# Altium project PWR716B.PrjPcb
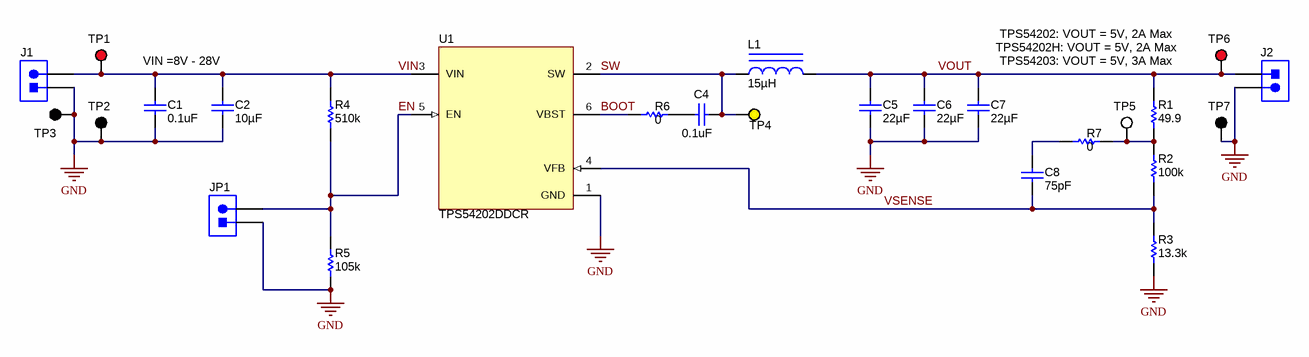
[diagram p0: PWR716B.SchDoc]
TID: N/A; TechSupport: http://www.ti.com/support; SCH_Rev: B; PRJ_Title: TPS54202EVM-716; PRJ_Number: PWR716; PRJ_Engineer: Abull Yang; PRJ_Customer: Public Release; PCB_Rev: B; PCB_Layout: Abull Yang; CopyrightYear: 2019
2 sheets, 40 parts. Net scope: global (net labels, ports and power ports of the same name join across sheets).
Board file: PWR716B.PcbDoc
Sheets:
  PWR716B.SchDoc
  PWR716B_Hardware.SchDoc

## Sheet PWR716B.SchDoc: PWR716
size 431 x 279 mm; VersionControl_RevNumber: A; Date: Not shown in title block; ApprovedBy: Not shown in title block; CheckedBy: Not shown in title block; Author: Not shown in title block; CompanyName: Not shown in title block; DrawnBy: Abull Yang; Engineer: Abull Yang; Organization: Not shown in title block; Address1: Not shown in title block; Address2: Not shown in title block; Address3: Not shown in title block; Address4: Not shown in title block; DocumentNumber: 1; Revision: Use project parameter SCH_Rev; SheetNumber: 1; SheetTotal: 1; PageSetup: Record=PageOptions¦CenterHorizontal=True¦CenterVertical=True¦PrintScale=1.00¦XCorrection=1.00¦YCorrection=1.00¦PrintKind=0¦BorderSize=5000000¦LeftOffset=0¦BottomOffset=0¦Orientation=2¦PaperLength=1000¦PaperWidth=1000¦Scale=100¦PaperSource=15¦PrintQuality=600¦MediaType=1¦DitherType=10¦PaperKind=Letter¦PrintScaleMode=1

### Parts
C1  ValueDisplayed: 0.1uF  [0603]  (hidden comment: GRM188R61E104KA01D)
C2  ValueDisplayed: 10µF  [1210]  (hidden comment: GRM32ER7YA106KA12L)
C4  0.1uF  [0603]
C5  ValueDisplayed: 22µF  [1210]  (hidden comment: GRM32ER71E226KE15L)
C6  ValueDisplayed: 22µF  [1210]  (hidden comment: GRM32ER71E226KE15L)
C7  ValueDisplayed: 22µF  [1210]  (hidden comment: GRM32ER71E226KE15L)
C8  ValueDisplayed: 75pF  [0603]  (hidden comment: GRM1885C1H750JA01D)
J1  ED555/2DS  [TERM_BLK_ED555-2DS]  (value not drawn)
J2  ED555/2DS  [TERM_BLK_ED555-2DS]  (value not drawn)
JP1  TSW-102-07-G-S  [TSW-102-07-G-S]  (value not drawn)
L1  ValueDisplayed: 15µH  [WE-PD-1050]  (hidden comment: 7447714150)
R1  ValueDisplayed: 49.9  [0603]  (hidden comment: CRCW060349R9FKEA)
R2  ValueDisplayed: 100k  [0603]  (hidden comment: CRCW0603100KFKEA)
R3  ValueDisplayed: 13.3k  [0603]  (hidden comment: CRCW060313K3FKEA)
R4  ValueDisplayed: 510k  [0603]  (hidden comment: CRCW0603510KJNEA)
R5  ValueDisplayed: 105k  [0603]  (hidden comment: CRCW0603105KFKEA)
R6  value 0  [0603]  (hidden comment: ERJ-3GEY0R00V)
R7  value 0  [0603]  (hidden comment: ERJ-3GEY0R00V)
TP1  5000  [Keystone5000]  (value not drawn)
TP2  5001  [Keystone5001]  (value not drawn)
TP3  5001  [Keystone5001]  (value not drawn)
TP4  5004  [Keystone5004]  (value not drawn)
TP5  5002  [Keystone5002]  (value not drawn)
TP6  5000  [Keystone5000]  (value not drawn)
TP7  5001  [Keystone5001]  (value not drawn)
U1  TPS54202DDCR  [DDC0006A_N]

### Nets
GND: C1.2 C2.1 C5.1 C6.1 C7.1 J1.1 J2.2 JP1.1 R3.1 R5.1 TP2.1 TP3.1 TP7.1 U1.1(GND)
BOOT: R6.1 U1.6(VBST)
EN: JP1.2 R4.1 R5.2 U1.5(EN)
SW: C4.2 L1.1 TP4.1 U1.2(SW)
VIN: C1.1 C2.2 J1.2 R4.2 TP1.1 U1.3(VIN)
VOUT: C5.2 C6.2 C7.2 J2.1 L1.2 R1.2 TP6.1
VSENSE: C8.2 R2.1 R3.2 U1.4(VFB)
NetC4_1: C4.1 R6.2
NetC8_1: C8.1 R7.1
NetR1_1: R1.1 R2.2 R7.2 TP5.1

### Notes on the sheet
- TPS54202: VOUT = 5V, 2A Max
- VIN =8V - 28V
- TPS54202H: VOUT = 5V, 2A Max
- TPS54203: VOUT = 5V, 3A Max

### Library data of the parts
C1 C4 = GRM188R61E104KA01D: CAP, CERM, 0.1uF, 25V, +/-10%, X5R, 0603; Manufacturer: MuRata; Polarized: N; CompType: Capacitor; U/M: EA; Cap_F: 0.0000001; Tolerance_%: 10; Value1: Unknown; VDC_V: 25; TaMin_C: -55; TaMax_C: 85
C2 = GRM32ER7YA106KA12L: CAP, CERM, 10 µF, 35 V, +/- 10%, X7R, 1210; Manufacturer: MuRata; Polarized: N; CompType: Capacitor; Value: 10uF; U/M: EA; Cap_F: 0.00001; Tolerance_%: 10; Value1: Unknown; VDC_V: 35; Value2: 35V; TaMin_C: -55; TaMax_C: 125
C5-C7 = GRM32ER71E226KE15L: CAP, CERM, 22 µF, 25 V, +/- 10%, X7R, 1210; Manufacturer: MuRata; Polarized: N; CompType: Capacitor; Value: 22uF; U/M: EA; Cap_F: 0.000022; Tolerance_%: 10; Value1: Unknown; VDC_V: 25; Value2: 25V; TaMin_C: -55; TaMax_C: 125
C8 = GRM1885C1H750JA01D: CAP, CERM, 75 pF, 50 V, +/- 5%, C0G/NP0, 0603; Manufacturer: MuRata; Polarized: N; CompType: Capacitor; Value: 75pF; U/M: EA; Cap_F: 0.000000000075; Tolerance_%: 5; Value1: Unknown; VDC_V: 50; Value2: 50V; TaMin_C: -55; TaMax_C: 125
J1 J2 = ED555/2DS: Terminal Block, 6A, 3.5mm Pitch, 2-Pos, TH; Manufacturer: On-Shore Technology; SymbolCreator: a0412235; CompType: Connector; U/M: EA
JP1 = TSW-102-07-G-S: Header, 100mil, 2x1, Gold, TH; Manufacturer: Samtec; SymbolCreator: a0412235; U/M: EA
L1 = 7447714150: Inductor, Shielded Drum Core, Ferrite, 15 µH, 3.5 A, 0.036 ohm, SMD; Manufacturer: Wurth Elektronik; Value: 15uH; Ind_H: 15.0E-6; Imax_A: 3.5; Irms: 3.5A @ 40C rise; Isat: 4.1A @ 10% inductance drop; DCR_ohm: 0.036; Value2: 3.5A; AEC Category: Q200
R1 = CRCW060349R9FKEA: RES, 49.9, 1%, 0.1 W, 0603; Manufacturer: Vishay-Dale; CompType: Resistor; Value: 49.9; Value_Code: 49R9; Tolerance_%: 1; Power_W: 0.1; Value2: 0.1W; VDC_V: 75; TempCo: 100 ppm/C; EIA_Code: E96; U/M: EA
R2 = CRCW0603100KFKEA: RES, 100 k, 1%, 0.1 W, 0603; Manufacturer: Vishay-Dale; CompType: Resistor; Value: 100k; Res_ohm: 100000; Tolerance_%: 1; Power_W: 0.1; Value2: 0.1W; VDC_V: 75; TempCo: 100 ppm/C; EIA_Code: E96; U/M: EA; AEC Category: Q200
R3 = CRCW060313K3FKEA: RES, 13.3 k, 1%, 0.1 W, 0603; Manufacturer: Vishay-Dale; CompType: Resistor; Value: 13.3k; Res_ohm: 13300; Value_Code: 13k3; Tolerance_%: 1; Power_W: 0.1; Value2: 0.1W; VDC_V: 75; TempCo: 100 ppm/C; EIA_Code: E96; U/M: EA
R4 = CRCW0603510KJNEA: RES, 510 k, 5%, 0.1 W, 0603; Manufacturer: Vishay-Dale; CompType: Resistor; Value: 510k; Res_ohm: 510000; Tolerance_%: 5; Power_W: 0.1; Value2: 0.1W; VDC_V: 75; TempCo: 200 ppm/C; EIA_Code: E24; U/M: EA
R5 = CRCW0603105KFKEA: RES, 105 k, 1%, 0.1 W, 0603; Manufacturer: Vishay-Dale; CompType: Resistor; Value: 105k; Res_ohm: 105000; Tolerance_%: 1; Power_W: 0.1; Value2: 0.1W; VDC_V: 75; TempCo: 100 ppm/C; EIA_Code: E96; U/M: EA
R6 R7 = ERJ-3GEY0R00V: RES, 0 ohm, 5%, 0.1W, 0603; Manufacturer: Panasonic; CompType: Resistor; Value_Code: 0000; Tolerance_%: 5; Power_W: 0.1; VDC_V: 50; TempCo: 600 ppm/C; EIA_Code: E24; U/M: EA
TP1 TP6 = 5000: Test Point, Miniature, Red, TH; Manufacturer: Keystone; CompType: Test Point Loop; U/M: EA
TP2 TP3 TP7 = 5001: Test Point, Miniature, Black, TH; Manufacturer: Keystone; CompType: Test Point Loop; U/M: EA
TP4 = 5004: Test Point, Miniature, Yellow, TH; Manufacturer: Keystone; CompType: Test Point Loop; U/M: EA
TP5 = 5002: Test Point, Miniature, White, TH; Manufacturer: Keystone; CompType: Test Point Loop; U/M: EA
U1 = TPS54202DDCR: 4.5-V TO 28-V INPUT, 2-A OUTPUT, EMI FRIENDLY SYNCHRONUOUS STEP-DOWN CONVERTOR, DDC0006A; Alternate Manufacturer: Texas Instruments; SymbolCreator: Altium; CompType: IC; U/M: EA

## Sheet PWR716B_Hardware.SchDoc
size 431 x 279 mm; Date: Not shown in title block; ApprovedBy: Not shown in title block; CheckedBy: Not shown in title block; Author: Not shown in title block; CompanyName: Not shown in title block; Engineer: Not shown in title block; Organization: Not shown in title block; Address1: Not shown in title block; Address2: Not shown in title block; Address3: Not shown in title block; Address4: Not shown in title block; DocumentNumber: 1; Revision: Use project parameter SCH_Rev; SheetNumber: 1; SheetTotal: 1; PageSetup: Record=PageOptions¦CenterHorizontal=True¦CenterVertical=True¦PrintScale=1.00¦XCorrection=1.00¦YCorrection=1.00¦PrintKind=0¦BorderSize=5000000¦LeftOffset=0¦BottomOffset=0¦Orientation=2¦PaperLength=1000¦PaperWidth=1000¦Scale=100¦PaperSource=15¦PrintQuality=600¦MediaType=1¦DitherType=10¦PaperKind=Letter¦PrintScaleMode=1
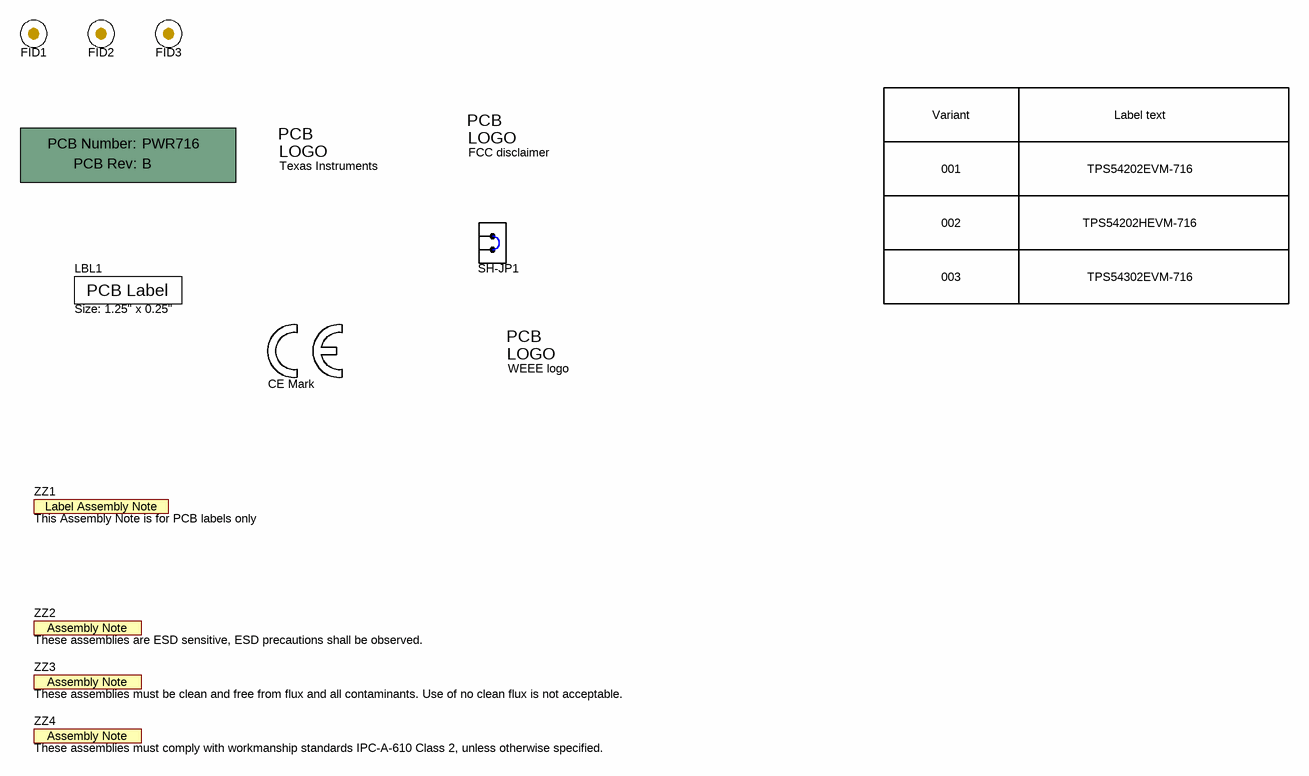
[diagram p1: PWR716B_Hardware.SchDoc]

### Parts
!PCB  Printed Circuit Board  (value not drawn)  (mechanical)
FID1  Fiducial  [Fiducial10-20]  (value not drawn)
FID2  Fiducial  [Fiducial10-20]  (value not drawn)
FID3  Fiducial  [Fiducial10-20]  (value not drawn)
LBL1  Size: 1.25" x 0.25"  [Label_1250x250]
Logo1  Texas Instruments  [TI_Stacked_Overlay_Small]  (no BOM)
Logo2  FCC disclaimer  [FCC_disclaimer]  (no BOM)
Logo3  CE Mark  [CE_Mark_5mm]  (no BOM)
Logo4  WEEE logo  [WEEE_Minimum]  (no BOM)
SH-JP1  382811-6  (value not drawn)  (mechanical)
ZZ1  This Assembly Note is for PCB labels only  [AssemblyNoteLabel]  (no BOM)
ZZ2  These assemblies are ESD sensitive, ESD precautions shall be observed.  [AssemblyNote]  (no BOM)
ZZ3  These assemblies must be clean and free from flux and all contaminants. Use of no clean flux is not acceptable.  [AssemblyNote]  (no BOM)
ZZ4  These assemblies must comply with workmanship standards IPC-A-610 Class 2, unless otherwise specified.  [AssemblyNote]  (no BOM)

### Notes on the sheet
- Variant
- Label text
- 001
- TPS54202EVM-716
- 002
- TPS54202HEVM-716
- 003
- TPS54302EVM-716

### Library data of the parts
!PCB = PCB: Manufacturer: Any; PartNumber: PWR716; SymbolCreator: a0412235
FID1-FID3 = Fiducial: Fiducial mark.  There is nothing to buy or mount.; SymbolCreator: codlsc
LBL1 = THT-13-457-10: Thermal Transfer Printable Labels, 1.250" W x 0.250" H - 10,000 per roll; Manufacturer: Brady; SymbolCreator: a0412235; CompType: Label
Logo1 = TI_Logo: Texas Instrument Corporate Signature; SymbolCreator: codlsc
Logo2 = FCC_disclaimer: SymbolCreator: codlsc
Logo3 = CMP-0074844-1: SymbolCreator: a0412235
Logo4 = CMP-0074769-1
SH-JP1 = 382811-6: Shunt, 100mil, Gold plated, Black; Manufacturer: AMP; Value: 1x2; Note: You can "mate" this to a header by matching the designator.  i.e. use SH-J3 for header J3
ZZ1 = AssemblyNoteLabel: SymbolCreator: a0412235
ZZ2-ZZ4 = AssemblyNote: SymbolCreator: codlsc

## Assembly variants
001: not fitted C7 FID1 FID2 FID3
002: not fitted C7 R5; alternate parts U1 -> TPS54202HDDC
003: not fitted C7; alternate parts U1 -> TPS54302DDC, L1 -> 7447714100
